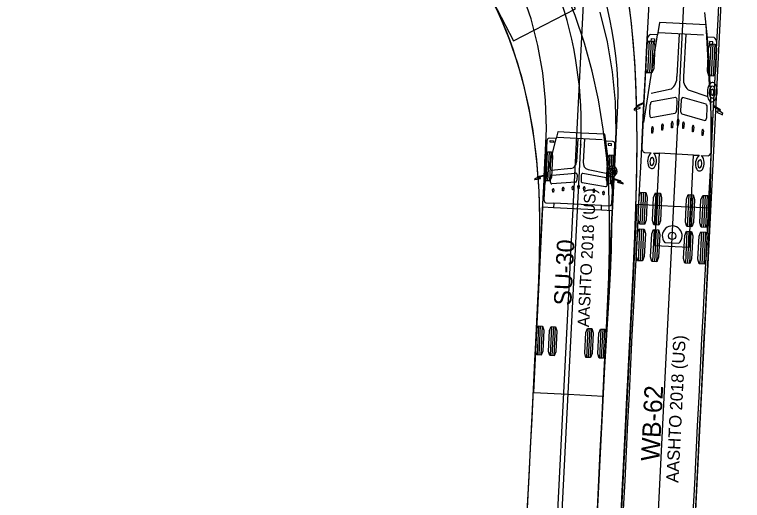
# Model space of a CAD drawing. Extents: x 260275 to 261282, y 610916 to 614143.
# Drawn here: x 261003.3 to 261086.7, y 612497.2 to 612553 of the extents above; entities that cross this region are included whole.
import ezdxf

# ---------------------------------------------------------------- set-up
doc = ezdxf.new("R2010")
doc.units = 0
doc.layers.add('GE_X_Alignment', color=7, linetype='Continuous')
doc.layers.add('TopoDOT_Transients', color=7, linetype='Continuous')

msp = doc.modelspace()

# ---------------------------------------------------------------- linework, layer by layer
at = {"layer": 'GE_X_Alignment'}
msp.add_line((260986.249, 610915.954), (261148.276, 614142.838), dxfattribs=at)
at = {"layer": 'TopoDOT_Transients'}
for p, q in [((261059.045, 612136.423), (261081.046, 612574.591)), ((261082.591, 612551.814), (261077.227, 612552.084)), ((261082.265, 612550.628), (261077.167, 612550.884)), ((261075.434, 612540.598), (261077.006, 612550.667)), ((261076.034, 612549.974), (261075.851, 612546.312)), ((261076.263, 612549.963), (261076.079, 612546.301)), ((261076.276, 612549.867), (261076.294, 612550.222)), ((261076.294, 612550.222), (261076.672, 612550.203)), ((261076.672, 612550.203), (261076.654, 612549.848)), ((261079.467, 612550.769), (261079.221, 612545.883)), ((261080.231, 612550.73), (261079.986, 612545.845)), ((261082.965, 612544.969), (261082.669, 612550.382)), ((261076.654, 612549.848), (261076.276, 612549.867)), ((261076.492, 612549.951), (261076.308, 612546.289)), ((261083.109, 612549.619), (261082.925, 612545.957)), ((261082.955, 612549.888), (261082.938, 612549.532)), ((261082.938, 612549.532), (261083.316, 612549.513)), ((261083.334, 612549.869), (261082.955, 612549.888)), ((261083.338, 612549.608), (261083.154, 612545.946)), ((261083.316, 612549.513), (261083.334, 612549.869)), ((261083.567, 612549.596), (261083.383, 612545.934)), ((261083.569, 612545.072), (261083.805, 612549.767)), ((261078.549, 612544.436), (261076.256, 612543.917)), ((261080.51, 612544.337), (261082.751, 612543.588)), ((261076.343, 612543.008), (261079.066, 612543.517)), ((261082.562, 612542.696), (261079.904, 612543.474)), ((261076.116, 612541.516), (261076.172, 612542.646)), ((261079.229, 612543.138), (261079.172, 612542.008)), ((261079.704, 612543.114), (261079.647, 612541.985)), ((261083.224, 612540.207), (261083.072, 612543.007)), ((261074.662, 612542.366), (261074.641, 612542.351)), ((261074.688, 612542.364), (261074.662, 612542.366)), ((261079.002, 612541.646), (261076.279, 612541.137)), ((261082.638, 612541.189), (261082.695, 612542.318)), ((261084.144, 612541.889), (261084.17, 612541.889)), ((261084.17, 612541.889), (261084.19, 612541.871)), ((261079.281, 612540.268), (261079.273, 612540.818)), ((261079.427, 612540.811), (261079.364, 612540.264)), ((261079.78, 612541.607), (261082.438, 612540.828)), ((261077.486, 612539.714), (261077.478, 612540.29)), ((261077.632, 612540.282), (261077.568, 612539.71)), ((261078.618, 612539.992), (261078.61, 612540.543)), ((261078.701, 612539.988), (261078.618, 612539.992)), ((261078.764, 612540.535), (261078.701, 612539.988)), ((261079.364, 612540.264), (261079.281, 612540.268)), ((261079.913, 612539.927), (261079.905, 612540.478)), ((261080.059, 612540.47), (261079.996, 612539.923)), ((261081.012, 612539.537), (261081.004, 612540.088)), ((261081.158, 612540.08), (261081.095, 612539.533)), ((261076.351, 612539.385), (261076.342, 612539.936)), ((261076.433, 612539.381), (261076.351, 612539.385)), ((261076.497, 612539.928), (261076.433, 612539.381)), ((261077.568, 612539.71), (261077.486, 612539.714)), ((261079.996, 612539.923), (261079.913, 612539.927)), ((261081.095, 612539.533), (261081.012, 612539.537)), ((261082.109, 612539.096), (261082.1, 612539.647)), ((261082.255, 612539.639), (261082.191, 612539.092)), ((261064.053, 612533.281), (261065.394, 612538.749)), ((261064.682, 612538.328), (261064.692, 612538.522)), ((261065.061, 612538.309), (261064.682, 612538.328)), ((261064.692, 612538.522), (261065.07, 612538.503)), ((261065.07, 612538.503), (261065.061, 612538.309)), ((261070.648, 612538.608), (261065.55, 612538.864)), ((261067.849, 612538.749), (261067.715, 612536.084)), ((261068.614, 612538.71), (261068.48, 612536.046)), ((261071.475, 612535.499), (261071.057, 612538.465)), ((261082.191, 612539.092), (261082.109, 612539.096)), ((261048.059, 612136.974), (261068.197, 612538.052)), ((261071.354, 612538.188), (261071.344, 612537.994)), ((261071.344, 612537.994), (261071.723, 612537.975)), ((261071.732, 612538.169), (261071.354, 612538.188)), ((261071.723, 612537.975), (261071.732, 612538.169)), ((261071.979, 612535.59), (261072.105, 612538.109)), ((261064.36, 612537.244), (261064.193, 612533.915)), ((261064.569, 612537.233), (261064.401, 612533.904)), ((261064.777, 612537.223), (261064.609, 612533.894)), ((261071.518, 612536.884), (261071.351, 612533.555)), ((261071.726, 612536.874), (261071.559, 612533.545)), ((261071.934, 612536.864), (261071.767, 612533.534)), ((261075.512, 612537.151), (261076.286, 612537.112)), ((261081.141, 612536.868), (261077.173, 612537.068)), ((261082.028, 612536.824), (261082.802, 612536.785)), ((261067.077, 612535.308), (261064.799, 612535.077)), ((261069.037, 612535.21), (261071.293, 612534.749)), ((261064.713, 612533.768), (261064.744, 612534.384)), ((261064.905, 612534.578), (261067.614, 612534.794)), ((261067.785, 612534.583), (261067.754, 612533.967)), ((261068.26, 612534.559), (261068.229, 612533.943)), ((261071.125, 612534.266), (261068.452, 612534.752)), ((261071.843, 612532.89), (261071.627, 612534.424)), ((261067.593, 612533.773), (261064.884, 612533.557)), ((261067.903, 612533.013), (261067.882, 612533.314)), ((261068.037, 612533.307), (261067.986, 612533.009)), ((261068.371, 612533.734), (261071.044, 612533.248)), ((261071.235, 612533.44), (261071.266, 612534.056)), ((261064.996, 612532.598), (261064.975, 612532.899)), ((261065.078, 612532.593), (261064.996, 612532.598)), ((261065.129, 612532.891), (261065.078, 612532.593)), ((261066.122, 612532.752), (261066.101, 612533.067)), ((261066.205, 612532.747), (261066.122, 612532.752)), ((261066.256, 612533.059), (261066.205, 612532.747)), ((261067.247, 612532.878), (261067.226, 612533.179)), ((261067.33, 612532.874), (261067.247, 612532.878)), ((261067.381, 612533.171), (261067.33, 612532.874)), ((261067.986, 612533.009), (261067.903, 612533.013)), ((261068.542, 612532.813), (261068.521, 612533.114)), ((261068.625, 612532.809), (261068.542, 612532.813)), ((261068.676, 612533.106), (261068.625, 612532.809)), ((261069.649, 612532.575), (261069.628, 612532.876)), ((261069.731, 612532.57), (261069.649, 612532.575)), ((261069.782, 612532.868), (261069.731, 612532.57)), ((261070.754, 612532.308), (261070.733, 612532.61)), ((261070.887, 612532.602), (261070.836, 612532.304)), ((261075.162, 612532.596), (261074.978, 612528.934)), ((261075.391, 612532.585), (261075.207, 612528.923)), ((261075.62, 612532.573), (261075.436, 612528.911)), ((261076.81, 612532.513), (261076.626, 612528.851)), ((261077.039, 612532.502), (261076.855, 612528.84)), ((261077.268, 612532.49), (261077.084, 612528.828)), ((261070.836, 612532.304), (261070.754, 612532.308)), ((261080.588, 612532.324), (261080.404, 612528.662)), ((261080.817, 612532.312), (261080.633, 612528.65)), ((261081.046, 612532.301), (261080.862, 612528.639)), ((261082.236, 612532.241), (261082.052, 612528.579)), ((261082.465, 612532.229), (261082.281, 612528.567)), ((261082.694, 612532.218), (261082.51, 612528.556)), ((261070.57, 612530.544), (261065.085, 612530.819)), ((261070.597, 612531.075), (261065.112, 612531.35)), ((261074.951, 612528.401), (261074.767, 612524.739)), ((261075.18, 612528.39), (261074.996, 612524.728)), ((261075.409, 612528.378), (261075.225, 612524.716)), ((261076.599, 612528.319), (261076.415, 612524.657)), ((261076.828, 612528.307), (261076.644, 612524.645)), ((261077.057, 612528.296), (261076.873, 612524.634)), ((261080.378, 612528.129), (261080.194, 612524.467)), ((261080.607, 612528.118), (261080.423, 612524.455)), ((261080.835, 612528.106), (261080.652, 612524.444)), ((261082.026, 612528.046), (261081.842, 612524.384)), ((261082.255, 612528.035), (261082.071, 612524.373)), ((261082.483, 612528.023), (261082.3, 612524.361)), ((261077.838, 612526.825), (261079.453, 612526.744)), ((261063.358, 612517.269), (261063.19, 612513.94)), ((261063.566, 612517.259), (261063.398, 612513.929)), ((261063.774, 612517.248), (261063.606, 612513.919)), ((261064.856, 612517.194), (261064.688, 612513.865)), ((261065.064, 612517.183), (261064.897, 612513.854)), ((261065.272, 612517.173), (261065.105, 612513.844)), ((261069.017, 612516.985), (261068.85, 612513.656)), ((261069.225, 612516.974), (261069.058, 612513.645)), ((261069.433, 612516.964), (261069.266, 612513.635)), ((261070.515, 612516.91), (261070.348, 612513.58)), ((261070.723, 612516.899), (261070.556, 612513.57)), ((261070.931, 612516.889), (261070.764, 612513.56))]:
    msp.add_line(p, q, dxfattribs=at)
for points in [[(261079.835, 612600.368), (261080.491, 612599.152), (261081.102, 612597.929), (261081.668, 612596.702), (261082.192, 612595.472), (261082.673, 612594.239), (261083.112, 612593.003), (261083.511, 612591.764), (261083.869, 612590.522), (261084.187, 612589.276), (261084.466, 612588.024), (261084.706, 612586.763), (261084.907, 612585.493), (261085.066, 612584.215), (261085.183, 612582.93), (261085.256, 612581.638), (261085.285, 612580.339), (261085.268, 612579.036), (261084.738, 612568.348), (261084.74, 612565.962), (261084.698, 612563.575), (261084.616, 612561.187), (261082.631, 612521.243), (261060.03, 612071.291)], [(261050.755, 612569.488), (261051.55, 612569.901), (261051.555, 612569.899), (261051.798, 612569.432), (261051.788, 612569.426), (261050.685, 612568.853), (261060.502, 612549.965), (261064.052, 612551.81), (261067.601, 612553.654), (261057.784, 612572.542), (261056.681, 612571.969), (261056.671, 612571.965), (261056.428, 612572.432), (261056.429, 612572.437), (261057.224, 612572.85)], [(261070.103, 612496.242), (261070.27, 612499.57), (261070.437, 612502.898), (261070.605, 612506.227), (261070.772, 612509.555), (261070.939, 612512.884), (261071.106, 612516.212), (261071.272, 612519.547), (261071.418, 612522.915), (261071.509, 612526.305), (261071.514, 612529.703), (261071.409, 612533.1), (261071.172, 612536.485), (261070.787, 612539.85), (261070.242, 612543.183), (261069.525, 612546.474), (261068.629, 612549.712), (261067.551, 612552.883), (261066.286, 612555.977)], [(261073.106, 612496.214), (261073.273, 612499.543), (261073.44, 612502.873), (261073.607, 612506.202), (261073.774, 612509.532), (261073.941, 612512.862), (261074.109, 612516.191), (261074.276, 612519.521), (261074.443, 612522.85), (261074.61, 612526.18), (261074.777, 612529.509), (261074.945, 612532.839), (261075.112, 612536.168), (261075.279, 612539.498), (261075.446, 612542.827), (261075.613, 612546.157), (261075.78, 612549.487), (261075.948, 612552.816), (261076.115, 612556.146)], [(261062.113, 612496.643), (261062.28, 612499.971), (261062.447, 612503.3), (261062.615, 612506.628), (261062.782, 612509.956), (261062.949, 612513.285), (261063.116, 612516.613), (261063.282, 612519.937), (261063.424, 612523.215), (261063.51, 612526.439), (261063.515, 612529.607), (261063.418, 612532.719), (261063.204, 612535.775), (261062.86, 612538.772), (261062.379, 612541.709), (261061.752, 612544.58), (261060.977, 612547.38), (261060.049, 612550.103), (261058.969, 612552.742), (261057.735, 612555.289)], [(261062.113, 612496.647), (261062.281, 612499.975), (261062.448, 612503.304), (261062.615, 612506.632), (261062.782, 612509.961), (261062.949, 612513.289), (261063.116, 612516.618), (261063.283, 612519.946), (261063.45, 612523.274), (261063.618, 612526.603), (261063.785, 612529.931), (261063.952, 612533.26), (261064.119, 612536.588), (261064.254, 612539.883), (261064.174, 612543.118), (261063.853, 612546.306), (261063.293, 612549.437), (261062.499, 612552.496), (261061.479, 612555.469)], [(261081.095, 612495.813), (261081.263, 612499.142), (261081.43, 612502.472), (261081.597, 612505.801), (261081.764, 612509.131), (261081.931, 612512.46), (261082.099, 612515.79), (261082.266, 612519.119), (261082.433, 612522.449), (261082.6, 612525.779), (261082.767, 612529.108), (261082.934, 612532.438), (261083.102, 612535.767), (261083.269, 612539.097), (261083.436, 612542.426), (261083.603, 612545.756), (261083.77, 612549.085), (261083.938, 612552.415), (261084.105, 612555.744)], [(261072.831, 612495.734), (261072.998, 612499.064), (261073.166, 612502.393), (261073.333, 612505.723), (261073.5, 612509.052), (261073.667, 612512.382), (261073.834, 612515.711), (261074, 612519.031), (261074.161, 612522.325), (261074.311, 612525.581), (261074.443, 612528.791), (261074.55, 612531.951), (261074.623, 612535.054), (261074.655, 612538.098), (261074.64, 612541.078), (261074.569, 612543.991), (261074.44, 612546.834), (261074.245, 612549.603), (261073.983, 612552.295), (261073.65, 612554.907)], [(261071.183, 612553.869), (261071.505, 612552.469), (261071.781, 612551.062), (261072.01, 612549.648), (261072.191, 612548.23), (261072.324, 612546.809), (261072.407, 612545.386), (261072.44, 612543.963), (261072.421, 612542.541), (261071.733, 612528.692), (261071.668, 612525.973), (261071.567, 612523.266), (261071.425, 612520.571), (261070.923, 612512.551), (261050.75, 612110.806)], [(261051.548, 612071.863), (261074.206, 612523.277), (261074.43, 612528.435), (261074.59, 612533.467), (261074.637, 612535.929), (261074.656, 612538.352), (261074.644, 612540.735), (261074.598, 612543.075), (261074.515, 612545.371), (261074.391, 612547.621), (261074.227, 612549.824), (261074.018, 612551.977), (261073.764, 612554.08)], [(261042.767, 612111.356), (261063.016, 612514.614), (261063.397, 612522.523), (261063.483, 612525.113), (261063.523, 612527.669), (261063.505, 612530.191), (261063.42, 612532.678), (261063.35, 612533.908), (261063.26, 612535.129), (261063.149, 612536.341), (261063.018, 612537.543), (261062.865, 612538.736), (261062.69, 612539.919), (261062.492, 612541.092), (261062.272, 612542.255), (261062.028, 612543.407), (261061.76, 612544.549), (261061.468, 612545.679), (261061.152, 612546.797), (261060.812, 612547.903), (261060.448, 612548.997), (261060.059, 612550.077), (261059.645, 612551.144), (261059.207, 612552.197), (261058.745, 612553.236)], [(261070.103, 612496.246), (261070.271, 612499.574), (261070.438, 612502.903), (261070.605, 612506.231), (261070.772, 612509.559), (261070.939, 612512.888), (261071.106, 612516.216), (261071.273, 612519.545), (261071.44, 612522.873), (261071.608, 612526.202), (261071.775, 612529.53), (261071.942, 612532.859), (261072.109, 612536.187), (261072.246, 612539.553), (261072.167, 612542.982), (261071.837, 612546.425), (261071.256, 612549.86), (261070.426, 612553.264)], [(261081.32, 612495.308), (261081.488, 612498.638), (261081.655, 612501.967), (261081.822, 612505.297), (261081.989, 612508.626), (261082.156, 612511.956), (261082.324, 612515.285), (261082.49, 612518.609), (261082.651, 612521.918), (261082.803, 612525.205), (261082.937, 612528.466), (261083.046, 612531.699), (261083.122, 612534.9), (261083.155, 612538.065), (261083.139, 612541.191), (261083.065, 612544.274), (261082.926, 612547.311), (261082.717, 612550.298), (261082.431, 612553.229)], [(261082.591, 612551.814), (261077.227, 612552.084), (261077.006, 612550.667), (261076.192, 612550.707)], [(261083.483, 612550.341), (261082.669, 612550.382), (261082.592, 612551.802)], [(261075.815, 612550.168), (261075.45, 612542.9), (261074.693, 612542.569)], [(261074.706, 612542.482), (261074.706, 612542.482), (261075.445, 612542.801), (261075.19, 612537.726)], [(261084.159, 612542.094), (261083.44, 612542.499), (261083.468, 612543.072)], [(261074.646, 612542.438), (261074.641, 612542.351), (261074.334, 612542.125), (261074.328, 612542.005), (261075.002, 612542.229), (261075.007, 612542.332), (261074.688, 612542.364), (261074.692, 612542.445)], [(261083.18, 612537.324), (261083.435, 612542.4), (261084.138, 612542.008), (261084.138, 612542.008)], [(261084.148, 612541.971), (261084.144, 612541.889), (261083.823, 612541.889), (261083.818, 612541.786), (261084.466, 612541.495), (261084.472, 612541.616), (261084.19, 612541.871), (261084.193, 612541.958)], [(261071.867, 612538.424), (261071.061, 612538.465), (261071.056, 612538.469), (261070.947, 612539.247), (261070.905, 612539.251), (261068.264, 612539.384), (261065.624, 612539.517), (261065.582, 612539.517), (261065.395, 612538.754), (261065.39, 612538.749), (261064.583, 612538.79)], [(261064.315, 612538.5), (261064.118, 612534.572), (261064.111, 612534.56), (261063.269, 612534.376), (261063.268, 612534.376)], [(261076.543, 612537.099), (261077.173, 612537.068), (261076.641, 612526.481), (261080.61, 612526.282), (261081.141, 612536.868), (261081.771, 612536.837)], [(261063.224, 612534.305), (261063.221, 612534.258), (261063.22, 612534.257), (261062.919, 612534.141), (261062.916, 612534.076), (261062.919, 612534.076), (261063.581, 612534.182), (261063.584, 612534.183), (261063.587, 612534.239), (261063.584, 612534.239), (261063.268, 612534.263), (261063.267, 612534.264), (261063.27, 612534.308)], [(261063.282, 612534.328), (261063.283, 612534.328), (261064.11, 612534.506), (261064.114, 612534.494), (261063.975, 612531.723)], [(261071.765, 612531.332), (261071.904, 612534.103), (261071.909, 612534.114), (261072.715, 612533.854), (261072.715, 612533.854)], [(261072.734, 612533.9), (261072.733, 612533.901), (261071.914, 612534.168), (261071.908, 612534.181), (261071.919, 612534.408)], [(261072.725, 612533.833), (261072.724, 612533.789), (261072.723, 612533.789), (261072.406, 612533.796), (261072.403, 612533.796), (261072.4, 612533.74), (261072.403, 612533.739), (261073.051, 612533.567), (261073.054, 612533.567), (261073.057, 612533.632), (261072.769, 612533.778), (261072.769, 612533.778), (261072.771, 612533.826)], [(261064.213, 612531.395), (261065.108, 612531.35), (261065.111, 612531.346), (261065.085, 612530.82), (261065.074, 612530.82), (261063.832, 612530.882), (261062.765, 612509.622), (261066.76, 612509.422), (261070.755, 612509.221), (261071.822, 612530.481), (261070.581, 612530.543), (261070.57, 612530.545), (261070.596, 612531.071), (261070.6, 612531.075), (261071.495, 612531.03)], [(261080.675, 612482.894), (261080.697, 612482.893), (261083.101, 612530.762), (261078.856, 612530.976), (261074.611, 612531.189), (261072.208, 612483.32), (261072.23, 612483.318)]]:
    msp.add_lwpolyline(points, dxfattribs=at)
for points in [[(261075.978, 612549.977), (261076.549, 612549.948), (261076.695, 612549.427), (261076.563, 612546.79), (261076.365, 612546.286), (261075.794, 612546.315), (261075.647, 612546.836), (261075.78, 612549.473)], [(261083.052, 612549.622), (261083.623, 612549.593), (261083.77, 612549.072), (261083.637, 612546.435), (261083.439, 612545.931), (261082.868, 612545.96), (261082.722, 612546.481), (261082.854, 612549.118)], [(261064.309, 612537.246), (261064.828, 612537.22), (261064.961, 612536.746), (261064.841, 612534.349), (261064.661, 612533.891), (261064.142, 612533.917), (261064.009, 612534.391), (261064.129, 612536.788)], [(261071.467, 612536.887), (261071.986, 612536.861), (261072.119, 612536.387), (261071.999, 612533.99), (261071.819, 612533.532), (261071.299, 612533.558), (261071.166, 612534.032), (261071.287, 612536.429)], [(261075.105, 612532.599), (261075.676, 612532.57), (261075.823, 612532.049), (261075.69, 612529.412), (261075.492, 612528.908), (261074.921, 612528.937), (261074.775, 612529.458), (261074.907, 612532.095)], [(261076.753, 612532.516), (261077.324, 612532.488), (261077.471, 612531.966), (261077.338, 612529.33), (261077.14, 612528.826), (261076.569, 612528.854), (261076.423, 612529.376), (261076.555, 612532.012)], [(261080.532, 612532.327), (261081.103, 612532.298), (261081.249, 612531.777), (261081.117, 612529.14), (261080.919, 612528.636), (261080.348, 612528.665), (261080.201, 612529.186), (261080.334, 612531.823)], [(261082.179, 612532.244), (261082.751, 612532.215), (261082.897, 612531.694), (261082.765, 612529.057), (261082.567, 612528.553), (261081.996, 612528.582), (261081.849, 612529.103), (261081.982, 612531.74)], [(261074.894, 612528.404), (261075.466, 612528.376), (261075.612, 612527.854), (261075.48, 612525.218), (261075.282, 612524.714), (261074.711, 612524.742), (261074.564, 612525.264), (261074.697, 612527.9)], [(261076.542, 612528.322), (261077.114, 612528.293), (261077.26, 612527.772), (261077.128, 612525.135), (261076.93, 612524.631), (261076.358, 612524.66), (261076.212, 612525.181), (261076.345, 612527.818)], [(261080.321, 612528.132), (261080.892, 612528.103), (261081.039, 612527.582), (261080.906, 612524.945), (261080.708, 612524.441), (261080.137, 612524.47), (261079.991, 612524.991), (261080.123, 612527.628)], [(261081.969, 612528.049), (261082.54, 612528.02), (261082.687, 612527.499), (261082.554, 612524.862), (261082.356, 612524.358), (261081.785, 612524.387), (261081.639, 612524.908), (261081.771, 612527.545)], [(261063.306, 612517.272), (261063.825, 612517.245), (261063.958, 612516.772), (261063.838, 612514.375), (261063.658, 612513.916), (261063.139, 612513.942), (261063.006, 612514.416), (261063.126, 612516.813)], [(261064.804, 612517.196), (261065.323, 612517.17), (261065.456, 612516.696), (261065.336, 612514.299), (261065.156, 612513.841), (261064.637, 612513.867), (261064.504, 612514.341), (261064.624, 612516.738)], [(261068.965, 612516.987), (261069.485, 612516.961), (261069.618, 612516.487), (261069.498, 612514.09), (261069.318, 612513.632), (261068.798, 612513.658), (261068.665, 612514.132), (261068.786, 612516.529)], [(261070.464, 612516.912), (261070.983, 612516.886), (261071.116, 612516.412), (261070.996, 612514.015), (261070.816, 612513.557), (261070.296, 612513.583), (261070.163, 612514.057), (261070.284, 612516.454)]]:
    msp.add_lwpolyline(points, close=True, dxfattribs=at)
for centre, radius in [((261068.197, 612538.052), 0.0417), ((261068.197, 612538.052), 0.0417), ((261071.804, 612535.006), 0.374), ((261071.804, 612535.006), 0.193), ((261078.686, 612527.592), 0.424)]:
    msp.add_circle(centre, radius, dxfattribs=at)
for centre, radius, start, end in [((261023.254, 612540.309), 45, 357.1255, 87.13462), ((261076.593, 612550.025), 0.792, 120.43659, 169.59206), ((261083.016, 612549.702), 0.792, 4.65895, 53.81442), ((261077.595, 612545.758), 1.631, 305.80134, 4.39207), ((261081.591, 612545.558), 1.631, 169.85894, 228.44967), ((261083.843, 612544.35), 1.074, 138.58211, 162.85096), ((261083.333, 612544.821), 0.38, 90.45588, 140.97941), ((261083.308, 612544.874), 0.328, 37.21385, 86.11819), ((261083.051, 612544.574), 0.719, 15.6559, 43.91288), ((261084.76, 612544.017), 2.049, 161.50654, 177.43184), ((261084.029, 612544.065), 1.098, 150.39127, 178.28386), ((261083.318, 612544.498), 0.268, 92.19814, 155.87577), ((261083.713, 612544.059), 0.617, 169.4131, 202.60389), ((261083.376, 612544.177), 0.27, 108.27444, 181.01824), ((261083.216, 612544.227), 0.22, 8.13535, 69.83363), ((261083.176, 612544.379), 0.407, 8.35614, 71.16055), ((261082.82, 612544.108), 0.631, 330.93378, 13.73431), ((261082.384, 612544.133), 1.234, 356.75519, 14.33734), ((261082.104, 612544.212), 1.731, 3.5106, 18.70836), ((261081.633, 612544.166), 2.204, 344.32456, 3.95974), ((261078.894, 612543.224), 0.342, 348.72731, 58.65379), ((261080.045, 612543.166), 0.342, 115.59721, 185.52369), ((261084.722, 612543.995), 2.012, 176.76687, 195.44978), ((261083.561, 612543.638), 0.799, 192.92493, 232.19257), ((261083.84, 612544.001), 0.914, 173.95993, 216.01791), ((261083.251, 612543.594), 0.199, 220.92879, 321.5681), ((261083.261, 612543.847), 0.12, 192.10162, 337.57965), ((261082.703, 612544.052), 0.913, 320.43513, 0.69541), ((261082.85, 612543.758), 0.924, 312.02262, 348.30076), ((261074.757, 612542.5), 0.127, 145.02093, 209.23008), ((261074.672, 612542.558), 0.0244, 27.99309, 141.30746), ((261074.597, 612542.5), 0.11, 330.07302, 350.18134), ((261076.575, 612542.678), 0.403, 125.12521, 184.58316), ((261082.298, 612542.39), 0.403, 349.66784, 49.12579), ((261083.234, 612543.26), 0.301, 237.35677, 321.25506), ((261078.775, 612541.972), 0.397, 304.88665, 3.04966), ((261080.038, 612541.908), 0.397, 171.20134, 229.36435), ((261084.248, 612542.016), 0.11, 184.06966, 204.17798), ((261084.179, 612542.08), 0.0244, 32.94354, 146.25791), ((261084.089, 612542.031), 0.127, 325.02093, 29.23008), ((261076.441, 612541.429), 0.334, 168.26267, 240.86063), ((261079.463, 612540.851), 0.192, 122.20119, 189.67576), ((261079.242, 612540.862), 0.192, 344.57524, 52.04981), ((261082.306, 612541.134), 0.334, 293.39037, 5.98833), ((261076.532, 612539.968), 0.192, 122.20119, 189.67576), ((261076.311, 612539.979), 0.192, 344.5479, 52.07716), ((261077.667, 612540.297), 0.192, 122.20119, 189.67576), ((261077.447, 612540.308), 0.192, 344.5479, 52.07716), ((261078.8, 612540.575), 0.192, 122.20119, 189.67576), ((261078.579, 612540.586), 0.192, 344.5479, 52.07716), ((261080.094, 612540.51), 0.192, 122.17384, 189.70311), ((261079.874, 612540.521), 0.192, 344.57524, 52.04981), ((261081.193, 612540.12), 0.192, 122.17384, 189.70311), ((261080.973, 612540.131), 0.192, 344.57524, 52.04981), ((261082.29, 612539.679), 0.192, 122.17384, 189.70311), ((261082.069, 612539.69), 0.192, 344.57524, 52.04981), ((261064.597, 612538.508), 0.282, 92.67391, 181.75333), ((261071.826, 612538.145), 0.282, 352.49767, 81.5771), ((261075.758, 612537.666), 0.571, 174.04089, 244.43248), ((261077.205, 612536.132), 1.344, 133.16094, 206.71574), ((261075.53, 612536.216), 1.344, 327.53526, 41.09006), ((261082.69, 612535.857), 1.344, 133.16094, 206.71574), ((261081.015, 612535.941), 1.344, 327.53526, 41.09006), ((261082.609, 612537.322), 0.571, 289.81853, 0.21012), ((261066.943, 612536.069), 0.773, 280.01597, 1.10013), ((261069.247, 612535.953), 0.773, 173.15088, 254.23504), ((261076.99, 612536.103), 0.86, 158.69148, 198.66086), ((261076.396, 612535.885), 0.228, 194.4278, 256.32264), ((261076.463, 612536.321), 0.29, 104.76976, 160.92979), ((261076.292, 612535.921), 0.262, 280.91747, 347.44267), ((261076.327, 612536.362), 0.247, 5.52911, 75.4082), ((261075.722, 612536.164), 0.879, 339.9934, 14.58864), ((261082.494, 612535.824), 0.879, 159.66236, 194.25761), ((261081.912, 612536.082), 0.247, 98.8428, 168.7219), ((261081.772, 612536.054), 0.29, 13.32121, 69.48124), ((261081.227, 612535.89), 0.86, 335.59014, 15.55953), ((261071.873, 612534.996), 0.63, 176.4803, 228.88311), ((261071.873, 612535.011), 0.629, 129.17109, 177.86038), ((261071.808, 612535.092), 0.526, 71.07067, 129.31667), ((261071.737, 612535.01), 0.628, 286.8788, 67.3705), ((261076.345, 612535.714), 0.387, 208.62104, 325.62996), ((261081.829, 612535.43), 0.383, 207.59628, 326.65472), ((261081.902, 612535.639), 0.262, 186.80834, 253.33353), ((261081.796, 612535.614), 0.228, 277.92836, 339.8232), ((261063.247, 612534.34), 0.0418, 59.61742, 236.63235), ((261063.241, 612534.34), 0.0434, 312.53921, 343.21198), ((261064.936, 612534.388), 0.193, 99.26792, 181.18241), ((261067.603, 612534.61), 0.184, 351.66723, 86.52737), ((261068.444, 612534.568), 0.184, 87.72364, 182.58377), ((261071.075, 612534.08), 0.193, 353.06859, 74.98308), ((261071.8, 612534.919), 0.524, 229.38452, 283.18459), ((261064.895, 612533.741), 0.184, 171.66167, 266.53293), ((261067.316, 612533.193), 0.091, 94.64508, 188.80895), ((261067.293, 612533.194), 0.0909, 345.40639, 79.64159), ((261067.562, 612533.963), 0.193, 279.26299, 1.18734), ((261067.972, 612533.328), 0.091, 94.64508, 188.80895), ((261067.948, 612533.33), 0.091, 345.44206, 79.60593), ((261068.42, 612533.92), 0.193, 173.06366, 254.98801), ((261071.051, 612533.432), 0.184, 267.71808, 2.58934), ((261072.758, 612533.862), 0.0434, 191.03902, 221.7118), ((261072.752, 612533.863), 0.0418, 297.61865, 114.63358), ((261065.065, 612532.913), 0.091, 94.64508, 188.80895), ((261065.041, 612532.914), 0.0909, 345.40639, 79.64159), ((261066.191, 612533.067), 0.091, 94.64508, 188.80895), ((261066.168, 612533.068), 0.0909, 345.40639, 79.64159), ((261068.611, 612533.128), 0.0909, 94.60942, 188.84462), ((261068.587, 612533.129), 0.091, 345.44206, 79.60593), ((261069.718, 612532.89), 0.0909, 94.60942, 188.84462), ((261069.694, 612532.891), 0.091, 345.44206, 79.60593), ((261070.823, 612532.624), 0.0909, 94.60942, 188.84462), ((261070.799, 612532.625), 0.091, 345.44206, 79.60593), ((261064.297, 612531.707), 0.323, 177.1255, 254.97391), ((261071.443, 612531.348), 0.323, 279.2771, 357.1255), ((261078.686, 612527.592), 1.143, 312.1255, 222.1255)]:
    msp.add_arc(centre, radius, start, end, dxfattribs=at)
for centre, major_axis, start_param, end_param in [((261074.669, 612542.504), (0.0039, 0.0781), 4.442794, 5.713538), ((261074.669, 612542.504), (-0.0039, -0.0781), 5.756759, 7.026061), ((261084.177, 612542.027), (-0.0039, -0.0781), 3.71124, 4.981984), ((261084.177, 612542.027), (0.0039, 0.0781), 2.398717, 3.668019)]:
    msp.add_ellipse(centre, major_axis=major_axis, ratio=0.5, start_param=start_param, end_param=end_param, dxfattribs=at)

# ---------------------------------------------------------------- texts
for s, height, p in [('AASHTO 2018 (US)', 1.33333, (261069.155, 612517.097)), ('SU-30', 2, (261067.109, 612519.56)), ('AASHTO 2018 (US)', 1.41667, (261079.397, 612499.243)), ('WB-62', 2.125, (261077.216, 612501.708))]:
    msp.add_text(s, height=height, rotation=87.1255, dxfattribs=at).set_placement(p)

doc.saveas('drawing.dxf')
